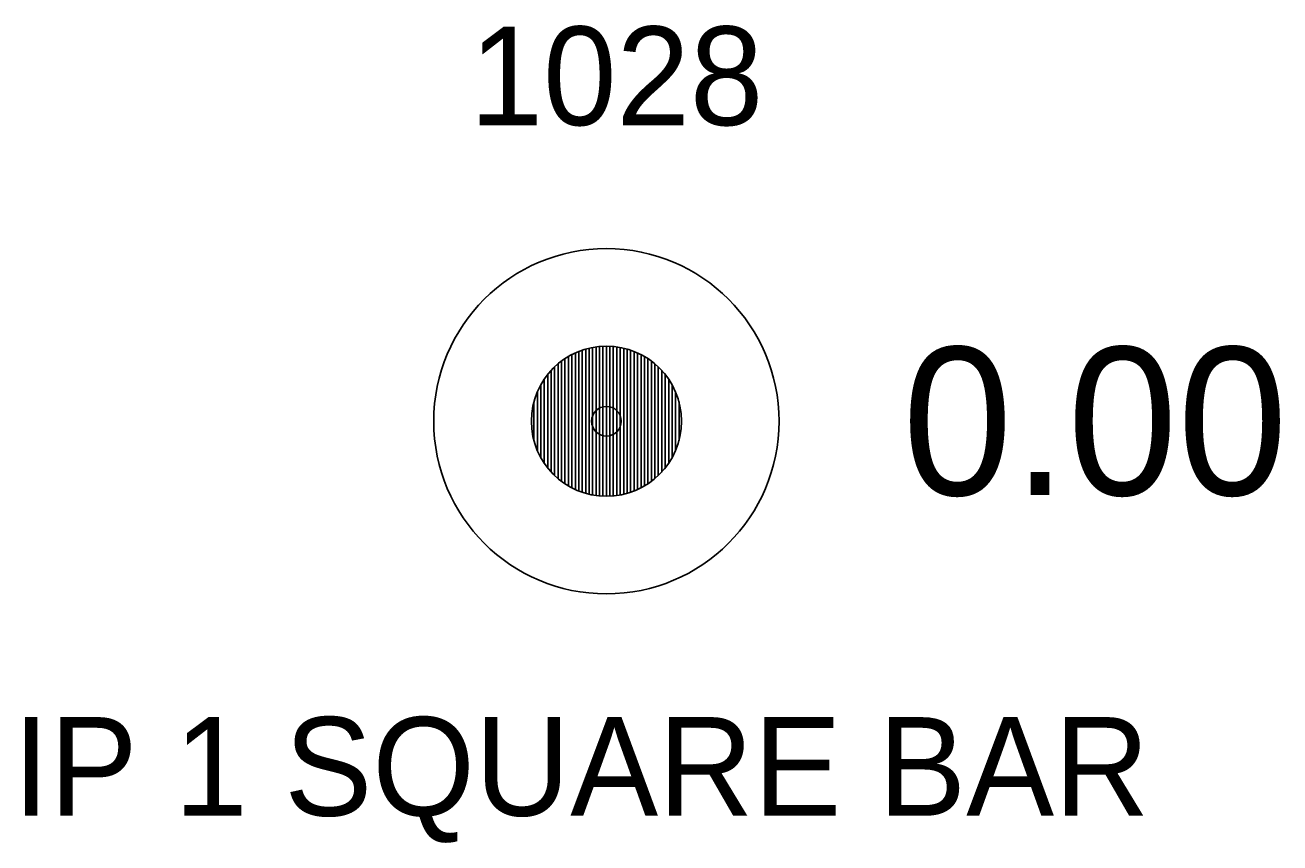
# Model space of a CAD drawing. Extents: x 1655137 to 1657928, y 1003994 to 1005407.
# Drawn here: x 1655623.91 to 1655636.63, y 1004715.69 to 1004723.98 of the extents above; entities that cross this region are included whole.
import ezdxf

# ---------------------------------------------------------------- set-up
doc = ezdxf.new("R2010")
doc.units = 0
for name, color, linetype in [('RD_EX_DV_Prop_txCode', 7, 'Continuous'), ('RD_EX_DV_PropPin', 7, 'Continuous'), ('RD_EX_TX_DV_Prop_ELEV', 7, 'Continuous'), ('RD_SMD_Locator', 7, 'Continuous')]:
    doc.layers.add(name, color=color, linetype=linetype)

msp = doc.modelspace()

# ---------------------------------------------------------------- linework, layer by layer
at = {"layer": 'RD_EX_DV_PropPin'}
for p, q in [((1655629.627, 1004719.225), (1655629.627, 1004720.706)), ((1655629.662, 1004719.217), (1655629.662, 1004720.714)), ((1655629.697, 1004719.212), (1655629.697, 1004720.719)), ((1655629.732, 1004719.208), (1655629.732, 1004720.723)), ((1655629.767, 1004719.205), (1655629.767, 1004720.726)), ((1655629.802, 1004719.204), (1655629.802, 1004720.727)), ((1655629.837, 1004719.205), (1655629.837, 1004720.726)), ((1655629.872, 1004719.208), (1655629.872, 1004720.723)), ((1655629.907, 1004719.212), (1655629.907, 1004720.719)), ((1655629.942, 1004719.217), (1655629.942, 1004720.714)), ((1655629.977, 1004719.225), (1655629.977, 1004720.706)), ((1655629.382, 1004719.331), (1655629.382, 1004720.6)), ((1655629.417, 1004719.309), (1655629.417, 1004720.622)), ((1655629.452, 1004719.29), (1655629.452, 1004720.641)), ((1655629.487, 1004719.273), (1655629.487, 1004720.658)), ((1655629.522, 1004719.258), (1655629.522, 1004720.673)), ((1655629.557, 1004719.245), (1655629.557, 1004720.686)), ((1655629.592, 1004719.234), (1655629.592, 1004720.697)), ((1655630.012, 1004719.234), (1655630.012, 1004720.697)), ((1655630.047, 1004719.245), (1655630.047, 1004720.686)), ((1655630.082, 1004719.258), (1655630.082, 1004720.673)), ((1655630.118, 1004719.273), (1655630.118, 1004720.658)), ((1655630.153, 1004719.29), (1655630.153, 1004720.641)), ((1655630.188, 1004719.309), (1655630.188, 1004720.622)), ((1655630.223, 1004719.331), (1655630.223, 1004720.6)), ((1655629.242, 1004719.45), (1655629.242, 1004720.481)), ((1655629.277, 1004719.415), (1655629.277, 1004720.516)), ((1655629.312, 1004719.383), (1655629.312, 1004720.548)), ((1655629.347, 1004719.356), (1655629.347, 1004720.575)), ((1655630.258, 1004719.356), (1655630.258, 1004720.575)), ((1655630.293, 1004719.383), (1655630.293, 1004720.548)), ((1655630.328, 1004719.415), (1655630.328, 1004720.516)), ((1655630.363, 1004719.45), (1655630.363, 1004720.481)), ((1655629.137, 1004719.596), (1655629.137, 1004720.335)), ((1655629.172, 1004719.539), (1655629.172, 1004720.392)), ((1655629.207, 1004719.491), (1655629.207, 1004720.44)), ((1655630.398, 1004719.491), (1655630.398, 1004720.44)), ((1655630.433, 1004719.539), (1655630.433, 1004720.392)), ((1655630.468, 1004719.596), (1655630.468, 1004720.335)), ((1655629.102, 1004719.668), (1655629.102, 1004720.263)), ((1655630.503, 1004719.668), (1655630.503, 1004720.263)), ((1655629.067, 1004719.769), (1655629.067, 1004720.162)), ((1655630.538, 1004719.769), (1655630.538, 1004720.162))]:
    msp.add_line(p, q, dxfattribs=at)
for radius in [1.75, 0.761]:
    msp.add_circle((1655629.802, 1004719.965), radius, dxfattribs=at)
at = {"layer": 'RD_SMD_Locator'}
msp.add_circle((1655629.802, 1004719.965), 0.15, dxfattribs=at)

# ---------------------------------------------------------------- texts
at = {"layer": 'RD_EX_DV_Prop_txCode'}
for s, p in [('1028', (1655628.417, 1004722.966)), ('IP 1 SQUARE BAR', (1655623.787, 1004715.966))]:
    msp.add_text(s, height=1, dxfattribs=at).set_placement(p)
at = {"layer": 'RD_EX_TX_DV_Prop_ELEV'}
msp.add_text('0.00', height=1.5, dxfattribs=at).set_placement((1655632.802, 1004719.216))

doc.saveas('drawing.dxf')
